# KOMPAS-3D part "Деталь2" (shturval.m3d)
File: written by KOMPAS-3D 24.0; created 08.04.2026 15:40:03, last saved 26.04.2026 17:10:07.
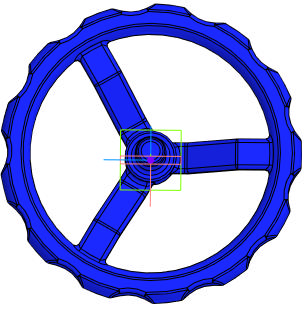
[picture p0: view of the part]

Document properties: Автор: R2D2; Полное имя файла: C:\Работа\VSO2130M-F-S Клапан запорный DN.ru\DN100\DN100\shturval.m3d

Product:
- Body: Твердое тело1  | qty 1
    Масса: 3.344958
- Part/product: Деталь2
    Масса: 3.344958
    additional columns: Типовые

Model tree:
1. Твердое тело1  (labels: Твердое тело1)
2. Масштабирование:1
3. Масштабирование : Твердое тело1
     Масштаб по оси Х = 1; Масштаб по оси Y = 1; Масштаб по оси Z = 1; Коэффициент = 1.69

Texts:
  Масштабирование : Вершина.Начало координат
